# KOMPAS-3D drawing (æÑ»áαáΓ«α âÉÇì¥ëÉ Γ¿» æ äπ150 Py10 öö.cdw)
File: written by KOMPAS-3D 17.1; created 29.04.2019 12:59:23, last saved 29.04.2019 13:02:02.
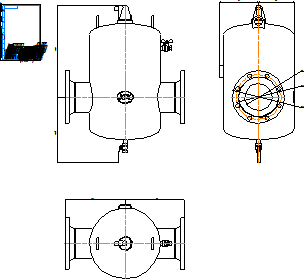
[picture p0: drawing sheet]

Sheet 1: A4, portrait

Title block, sheet 1: name: Сепаратор ГРАНЭЙР тип С / Ду150 Py10 ФФ; material: Внимание! Данный продукт является объектом авторского права ООО «Торговый Дом АДЛ». / Запрещается изменение, копирование, распространение / (в том числе путем копирования на другие сайты и ресурсы в Интернете) / или любое иное использование информации и объектов без предварительного / согласия правообладателя (ООО «Торговый Дом АДЛ»).; sheets: 1; organisation: ООО "Торговый дом АДЛ"; sheet format: A4

Views: Вид 1, Проекционный вид 2, Проекционный вид 3
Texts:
  user
Dimensions and other numbers on the sheet: 345,92; 484,56; 240; 317,5; 205; 188,5; 146; 280; 1:1; 1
